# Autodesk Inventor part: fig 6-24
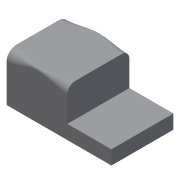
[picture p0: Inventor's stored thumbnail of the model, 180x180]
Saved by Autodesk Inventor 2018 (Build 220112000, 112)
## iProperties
Created: 2004-05
Part Number: fig 6-24
Document SubType Name: Modeling
Designer: CADCIM Technologies
Manufacturer: Standard
Standards Organization: Custom
Density: 1 g/cm^3
Material: Generic
Appearance: Default
Author: CADCIM Technologies
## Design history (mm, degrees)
node "Sketch1"
sketch "Sketch2"
  geometry: L1 (0.098, 47.711)-(0.098, 0.049); L2 (0.098, 0.049)-(-105.483, 0.049); L3 (-105.483, 0.049)-(-105.483, 14.192); L4 (-105.483, 14.192)-(-61.139, 14.192); L5 (-61.139, 14.192)-(-61.139, 47.711); L6 (-61.139, 47.711)-(0.098, 47.711)
  constraints: 12 end point, 3 parallel, 2 perpendicular, 1 vertical
extrude "Extrusion1" new body sketch "Sketch2" stored distance "d0" = 62.5; taper "d1" = 0 deg
fillet "Fillet9" dims "d61" = 10, "d62" = 8, "d63" = 2, "d64" = 5
fillet "Fillet10" dims "d65" = 8, "d66" = 10, "d67" = 2, "d68" = 5
body "Solid1"
